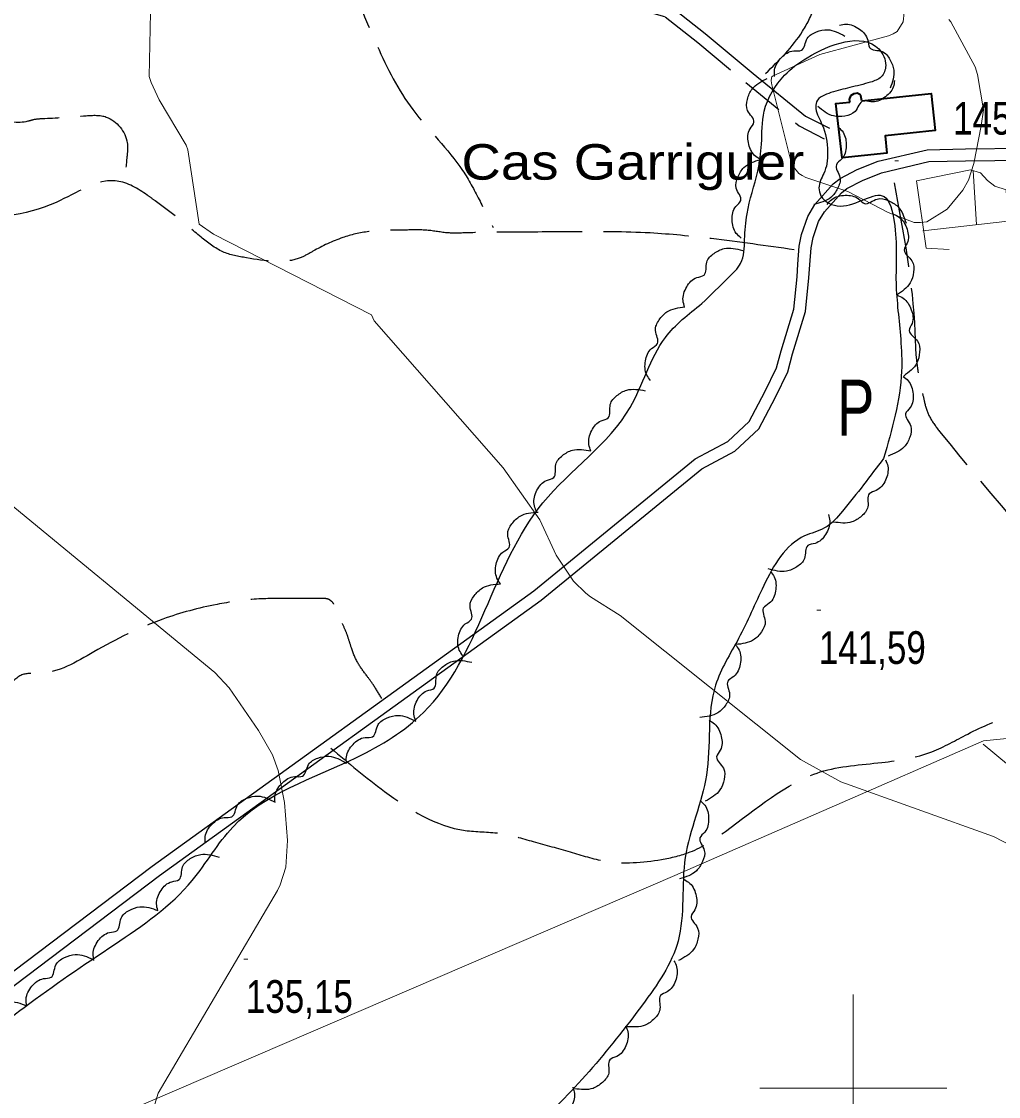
# Model space of a CAD drawing. Extents: x 483843 to 488449, y 4381269 to 4384483.
# Drawn here: x 485277.5 to 485538.8, y 4381997.7 to 4382285.4 of the extents above; entities that cross this region are included whole.
import ezdxf
from ezdxf.enums import TextEntityAlignment as Align

# ---------------------------------------------------------------- set-up
doc = ezdxf.new("R2010")
doc.units = 0
doc.header["$LTSCALE"] = 3.8
doc.linetypes.add('LONG_DASHED', pattern=[7.5, 6, -1.5])
doc.linetypes.add('MEDIUM_DASHED', pattern=[4.5, 3, -1.5])
for name, color, linetype, lineweight in [('1', 7, 'Continuous', 13), ('27', 7, 'Continuous', 25), ('38', 7, 'Continuous', 25), ('47', 7, 'Continuous', 35), ('51', 7, 'Continuous', 13), ('7', 7, 'Continuous', 13), ('9', 7, 'Continuous', 13)]:
    doc.layers.add(name, color=color, linetype=linetype, lineweight=lineweight)
doc.layers.add('31', color=7, linetype='Continuous')
doc.layers.add('5', color=7, linetype='Continuous')

msp = doc.modelspace()

# ---------------------------------------------------------------- linework, layer by layer
at = {"layer": '1'}
for p, q in [((485500, 4382025), (485500, 4381975)), ((485475, 4382000), (485525, 4382000))]:
    msp.add_line(p, q, dxfattribs=at)
at = {"layer": '27'}
for points in [[(485478.94, 4382270.69), (485478.95, 4382272.47), (485480.81, 4382275.77), (485484.07, 4382277.52), (485486.11, 4382277.69), (485487.7, 4382280.87), (485490.12, 4382282.61), (485493.09, 4382283.19), (485497.75, 4382281.5)], [(485496.32, 4382284.45), (485498.07, 4382284.71), (485501.63, 4382283.37), (485503.85, 4382280.42), (485504.33, 4382278.43), (485507.72, 4382277.35), (485509.81, 4382275.22), (485510.83, 4382272.37), (485509.87, 4382267.51)], [(485459.51, 4382209.91), (485466.62, 4382216.87), (485469.85, 4382220.68), (485470.94, 4382227.08), (485471.57, 4382233.91), (485474.44, 4382245.37), (485475.44, 4382252.59), (485476.18, 4382261.38), (485481.64, 4382271.01), (485487.63, 4382275.69), (485506.8, 4382278.06), (485508.68, 4382273.59), (485507.45, 4382270.57), (485504.63, 4382269.17), (485499.1, 4382267.72), (485494.02, 4382266.35), (485490.17, 4382263.88), (485489.97, 4382262.08), (485491.7, 4382257.76), (485493.1, 4382250.58), (485492.94, 4382247.35), (485492.08, 4382244.71), (485490.8, 4382240.86), (485491.36, 4382238.77), (485496.51, 4382236.01), (485508.25, 4382238.54), (485510.92, 4382231.84), (485511.44, 4382215.42), (485512.68, 4382200.43), (485512.91, 4382191.81), (485508.11, 4382168.47)], [(485475.04, 4382248.55), (485473.59, 4382249.58), (485471.95, 4382253), (485472.39, 4382256.67), (485473.42, 4382258.44), (485471.72, 4382261.57), (485471.68, 4382264.55), (485472.91, 4382267.31), (485476.97, 4382270.16)], [(485511.04, 4382269.59), (485510.68, 4382267.85), (485508.21, 4382264.97), (485504.68, 4382263.9), (485502.64, 4382264.13), (485500.46, 4382261.32), (485497.74, 4382260.09), (485494.72, 4382260.11), (485490.48, 4382262.68)], [(485496.08, 4382257.08), (485497.26, 4382255.75), (485498.11, 4382252.05), (485496.87, 4382248.57), (485495.47, 4382247.07), (485496.43, 4382243.65), (485495.8, 4382240.73), (485493.99, 4382238.31), (485489.4, 4382236.43)], [(485469.97, 4382227.45), (485468.7, 4382228.69), (485467.6, 4382232.32), (485468.6, 4382235.88), (485469.89, 4382237.47), (485468.69, 4382240.82), (485469.11, 4382243.77), (485470.75, 4382246.31), (485475.2, 4382248.51)], [(485493, 4382236.46), (485494.23, 4382237.76), (485497.84, 4382238.89), (485501.41, 4382237.93), (485503.02, 4382236.66), (485506.36, 4382237.89), (485509.32, 4382237.49), (485511.88, 4382235.89), (485514.12, 4382231.45)], [(485510.78, 4382233.82), (485512.34, 4382232.98), (485514.39, 4382229.79), (485514.42, 4382226.1), (485513.61, 4382224.21), (485515.69, 4382221.32), (485516.1, 4382218.36), (485515.22, 4382215.47), (485511.55, 4382212.14)], [(485454.89, 4382208.98), (485454.46, 4382210.7), (485455.43, 4382214.37), (485458.15, 4382216.87), (485460.09, 4382217.55), (485460.82, 4382221.03), (485462.74, 4382223.32), (485465.47, 4382224.62), (485470.41, 4382224.15)], [(485511.72, 4382212.15), (485513.32, 4382211.37), (485515.52, 4382208.28), (485515.71, 4382204.6), (485514.99, 4382202.67), (485517.2, 4382199.88), (485517.74, 4382196.95), (485517, 4382194.02), (485513.48, 4382190.52)], [(484798.92, 4381998.99), (484814.13, 4381997.5), (484843.2, 4381995.91), (484868.25, 4382000.56), (484887.51, 4382002.1), (484917.02, 4382005.25), (484964.05, 4382006.09), (484977.04, 4382005.57), (484983.34, 4382005.23), (485009.08, 4382005.54), (485023.48, 4382005.42), (485036.4, 4382004.83), (485065.6, 4382003.85), (485109.14, 4382007.17), (485145.01, 4382023.64), (485213.43, 4382058.32), (485219.23, 4382057.08), (485223.55, 4382050.33), (485223.76, 4382008.99), (485220.77, 4381999.7), (485221.24, 4381990.33), (485225.73, 4381986.51), (485231.26, 4381987.74), (485241.59, 4381993.47), (485278.23, 4382021.59), (485302.39, 4382038.45), (485323.17, 4382055.55), (485334.02, 4382069.85), (485367.08, 4382088.44), (485385.03, 4382100.47), (485416.97, 4382156.56), (485440.3, 4382182.11), (485449.72, 4382200.81), (485459.51, 4382209.91)], [(485445.79, 4382189.33), (485444.78, 4382190.8), (485444.39, 4382194.57), (485446.05, 4382197.87), (485447.62, 4382199.19), (485447.08, 4382202.7), (485448.06, 4382205.52), (485450.15, 4382207.7), (485454.94, 4382209.01)], [(485513.35, 4382190.43), (485514.69, 4382189.26), (485515.98, 4382185.69), (485515.19, 4382182.09), (485513.98, 4382180.42), (485515.37, 4382177.15), (485515.11, 4382174.17), (485513.61, 4382171.54), (485509.29, 4382169.11)], [(485429.81, 4382170.49), (485429.28, 4382172.19), (485430.02, 4382175.91), (485432.58, 4382178.57), (485434.47, 4382179.37), (485434.99, 4382182.89), (485436.76, 4382185.29), (485439.4, 4382186.76), (485444.36, 4382186.59)], [(485415.1, 4382154.54), (485414.59, 4382156.24), (485415.37, 4382159.95), (485417.96, 4382162.58), (485419.86, 4382163.36), (485420.42, 4382166.87), (485422.21, 4382169.26), (485424.87, 4382170.69), (485429.83, 4382170.47)], [(485508.11, 4382168.47), (485497.14, 4382154.39), (485492.34, 4382149.87), (485486.98, 4382147.75), (485476.04, 4382134.43), (485469.31, 4382120.28), (485463.15, 4382107.79), (485460.73, 4382083.73), (485455.05, 4382061.72), (485453.12, 4382039.33), (485443.59, 4382022.28), (485413.43, 4381988.65), (485371.07, 4381957.21), (485349.23, 4381936.26), (485331.41, 4381917.56), (485310.92, 4381892.36), (485301.95, 4381886.42), (485299.93, 4381877.68), (485296.95, 4381863.37), (485288.88, 4381857.75), (485280.91, 4381858.74), (485262.52, 4381888.42), (485260.4, 4381897.69), (485251.77, 4381956.74), (485244.54, 4381962.46), (485234.48, 4381967.01), (485223.41, 4381969.59), (485221.53, 4381969.55), (485200.04, 4381967.22), (485176.97, 4381960.51), (485150.46, 4381949.23), (485137.77, 4381941.58), (485118.97, 4381930.96), (485100.86, 4381928.77), (485070.67, 4381925.6), (485052.23, 4381924.67), (485034.52, 4381920.53), (485015.41, 4381919.37), (485007.52, 4381920.05), (484994.14, 4381921.24), (484952.93, 4381922.31)], [(485508.63, 4382168.07), (485509.22, 4382166.4), (485508.61, 4382162.65), (485506.15, 4382159.9), (485504.29, 4382159.03), (485503.89, 4382155.5), (485502.21, 4382153.03), (485499.62, 4382151.47), (485494.66, 4382151.46)], [(485405.62, 4382134.9), (485404.68, 4382136.41), (485404.48, 4382140.2), (485406.29, 4382143.41), (485407.92, 4382144.66), (485407.55, 4382148.19), (485408.66, 4382150.96), (485410.86, 4382153.04), (485415.7, 4382154.12)], [(485493.34, 4382153.5), (485493.7, 4382151.76), (485492.58, 4382148.13), (485489.77, 4382145.74), (485487.81, 4382145.14), (485486.93, 4382141.69), (485484.93, 4382139.48), (485482.15, 4382138.29), (485477.23, 4382138.96)], [(485477.86, 4382138.24), (485478.85, 4382136.77), (485479.2, 4382132.99), (485477.51, 4382129.71), (485475.93, 4382128.4), (485476.43, 4382124.88), (485475.43, 4382122.07), (485473.31, 4382119.91), (485468.51, 4382118.66)], [(485395.54, 4382115.68), (485394.61, 4382117.19), (485394.4, 4382120.98), (485396.21, 4382124.19), (485397.85, 4382125.44), (485397.48, 4382128.97), (485398.59, 4382131.74), (485400.78, 4382133.82), (485405.63, 4382134.9)], [(485468.44, 4382118.69), (485469.43, 4382117.21), (485469.75, 4382113.43), (485468.04, 4382110.16), (485466.44, 4382108.87), (485466.92, 4382105.34), (485465.89, 4382102.54), (485463.76, 4382100.4), (485458.95, 4382099.17)], [(485382.93, 4382098.29), (485382.45, 4382100), (485383.31, 4382103.69), (485385.95, 4382106.28), (485387.87, 4382107.01), (485388.5, 4382110.51), (485390.34, 4382112.86), (485393.03, 4382114.24), (485397.98, 4382113.92)], [(485364.44, 4382086.82), (485364.41, 4382088.6), (485366.17, 4382091.95), (485369.38, 4382093.79), (485371.42, 4382094.02), (485372.91, 4382097.24), (485375.29, 4382099.05), (485378.24, 4382099.71), (485382.95, 4382098.15)], [(485461.42, 4382098.42), (485462.9, 4382097.45), (485464.69, 4382094.1), (485464.41, 4382090.42), (485463.45, 4382088.6), (485465.28, 4382085.55), (485465.44, 4382082.57), (485464.33, 4382079.76), (485460.39, 4382076.74)], [(485345.27, 4382076.64), (485345.33, 4382078.42), (485347.27, 4382081.67), (485350.57, 4382083.33), (485352.62, 4382083.45), (485354.29, 4382086.59), (485356.76, 4382088.27), (485359.74, 4382088.77), (485364.36, 4382086.96)], [(485326.62, 4382065.53), (485326.63, 4382067.3), (485328.47, 4382070.62), (485331.71, 4382072.39), (485333.75, 4382072.58), (485335.31, 4382075.77), (485337.73, 4382077.53), (485340.69, 4382078.13), (485345.37, 4382076.47)], [(485459, 4382076.95), (485460.25, 4382075.7), (485461.31, 4382072.06), (485460.28, 4382068.51), (485458.97, 4382066.93), (485460.14, 4382063.57), (485459.68, 4382060.62), (485458.02, 4382058.1), (485453.54, 4382055.95)], [(485313.94, 4382047.54), (485313.62, 4382049.29), (485314.81, 4382052.89), (485317.67, 4382055.22), (485319.64, 4382055.79), (485320.59, 4382059.21), (485322.63, 4382061.39), (485325.44, 4382062.52), (485330.34, 4382061.75)], [(485454.81, 4382055.78), (485456.28, 4382054.77), (485457.98, 4382051.38), (485457.61, 4382047.71), (485456.61, 4382045.91), (485458.36, 4382042.82), (485458.45, 4382039.84), (485457.27, 4382037.05), (485453.26, 4382034.13)], [(485296.87, 4382034.14), (485296.64, 4382035.9), (485298.02, 4382039.44), (485300.99, 4382041.62), (485302.99, 4382042.08), (485304.12, 4382045.45), (485306.27, 4382047.52), (485309.13, 4382048.5), (485313.98, 4382047.49)], [(485278.85, 4382022.03), (485278.71, 4382023.8), (485280.28, 4382027.25), (485283.36, 4382029.28), (485285.39, 4382029.63), (485286.68, 4382032.94), (485288.95, 4382034.89), (485291.85, 4382035.72), (485296.65, 4382034.45)], [(485452.01, 4382034.08), (485452.73, 4382032.46), (485452.42, 4382028.68), (485450.19, 4382025.74), (485448.4, 4382024.73), (485448.28, 4382021.18), (485446.8, 4382018.58), (485444.34, 4382016.83), (485439.4, 4382016.42)], [(485261.6, 4382008.87), (485261.38, 4382010.63), (485262.79, 4382014.16), (485265.79, 4382016.31), (485267.8, 4382016.75), (485268.95, 4382020.11), (485271.13, 4382022.15), (485274, 4382023.11), (485278.84, 4382022.04)], [(485439.06, 4382016.68), (485439.69, 4382015.02), (485439.15, 4382011.26), (485436.74, 4382008.46), (485434.89, 4382007.56), (485434.57, 4382004.02), (485432.93, 4382001.52), (485430.37, 4381999.91), (485425.41, 4381999.81)], [(485424.95, 4382000.22), (485425.4, 4381998.51), (485424.47, 4381994.83), (485421.79, 4381992.29), (485419.86, 4381991.59), (485419.17, 4381988.1), (485417.29, 4381985.78), (485414.58, 4381984.45), (485409.63, 4381984.85)]]:
    msp.add_spline(points, degree=3, dxfattribs=at)
at = {"layer": '38'}
for points in [[(485435.92, 4382293.7), (485439.33, 4382292.86), (485451.11, 4382289.47), (485460.37, 4382282.19), (485473.24, 4382271.47), (485487.22, 4382260.09), (485493.63, 4382256.82)], [(485235.03, 4382000.84), (485312.48, 4382059.39), (485414.56, 4382133.08), (485457.71, 4382168.4), (485466.46, 4382173.04), (485472.13, 4382178.33), (485476.36, 4382186.32), (485479.5, 4382192.75), (485480.67, 4382197.29), (485484.08, 4382208.4), (485484.95, 4382217.04), (485485.19, 4382220.49), (485485.56, 4382225.26), (485486.12, 4382228.44), (485487.82, 4382233.25), (485489.71, 4382236.4), (485494.65, 4382241.92), (485496.53, 4382243.38), (485501.07, 4382245.75), (485506.61, 4382247.98), (485519.8, 4382251.09), (485530.01, 4382251.28), (485545.6, 4382251.48)], [(485236.96, 4381998.29), (485314.38, 4382056.83), (485416.5, 4382130.54), (485459.49, 4382165.73), (485468.33, 4382170.41), (485474.71, 4382176.36), (485479.21, 4382184.87), (485482.52, 4382191.64), (485483.76, 4382196.43), (485487.22, 4382207.77), (485488.14, 4382216.77), (485488.38, 4382220.26), (485488.74, 4382224.86), (485489.23, 4382227.63), (485490.72, 4382231.88), (485492.29, 4382234.49), (485496.84, 4382239.57), (485498.26, 4382240.68), (485502.42, 4382242.85), (485507.57, 4382244.93), (485520.2, 4382247.91), (485530.06, 4382248.08), (485545.69, 4382248.28)]]:
    msp.add_lwpolyline(points, dxfattribs=at)
at = {"layer": '38', "linetype": 'MEDIUM_DASHED'}
msp.add_lwpolyline([(485435.17, 4382290.68), (485438.52, 4382289.84), (485449.66, 4382286.64), (485458.41, 4382279.77), (485471.26, 4382269.06), (485485.51, 4382257.46), (485492.21, 4382254.04)], dxfattribs=at)
at = {"layer": '38', "linetype": 'LONG_DASHED'}
for points in [[(485476.53, 4382271.44), (485486.45, 4382282.8), (485489.78, 4382289.76), (485492.8, 4382330.78), (485507.2, 4382373.28), (485507.25, 4382395.64), (485506.93, 4382400.97), (485504.7, 4382412.63), (485509.62, 4382423), (485512.91, 4382427.71), (485519.46, 4382443.28), (485523.09, 4382454.75), (485524.19, 4382460.32), (485526.24, 4382475.89), (485527.73, 4382493.1), (485527.34, 4382498.05), (485527.57, 4382510.28), (485534.14, 4382529.16), (485535.62, 4382530.26)], [(485355.21, 4382332.66), (485360.95, 4382310.58), (485372.62, 4382278.9), (485382.16, 4382261.81), (485395.5, 4382245.54), (485399.92, 4382237.74), (485403.65, 4382230.31)], [(484788.33, 4382234.74), (484798.67, 4382230.05), (484803.24, 4382234.63), (484824.91, 4382247.7), (484836.04, 4382250.97), (484859.06, 4382259.93), (484874.65, 4382269.29), (484884.56, 4382273.37), (484899.83, 4382279.49), (484900.61, 4382282.21), (484903.87, 4382284.59), (484911.85, 4382286.98), (484915.45, 4382287.05), (484917.93, 4382287.09), (484921.74, 4382288.06), (484928.22, 4382290.95), (484942.69, 4382299.91), (484969.07, 4382306.01), (484978.82, 4382306.18), (484999.64, 4382308.28), (485005.36, 4382307.03), (485017.7, 4382301.17), (485026.64, 4382300.21), (485028.22, 4382300.23), (485050.5, 4382291.78), (485074.9, 4382295.36), (485078.11, 4382296.09), (485099.65, 4382296.25), (485110.05, 4382293.74), (485115.9, 4382293.69), (485123.47, 4382294.05), (485131.94, 4382294.8), (485145.49, 4382296.47), (485158.78, 4382295.88), (485165.4, 4382294.65), (485166.94, 4382292.8), (485169.07, 4382290.73), (485175.72, 4382288.08), (485189.84, 4382283.45), (485200.22, 4382277.78), (485213.12, 4382269.31), (485218.12, 4382266.85), (485223.91, 4382265.9), (485231.94, 4382265.82), (485237.5, 4382265.92), (485249.13, 4382265.67), (485262.09, 4382262.6), (485279.27, 4382258.78), (485280.83, 4382259.18), (485283.75, 4382259.46), (485294.77, 4382260.18), (485300.18, 4382259.83), (485305.78, 4382252.95), (485305.7, 4382249.2), (485305.14, 4382242.81)], [(485484.19, 4382224.31), (485462, 4382227.29), (485445.62, 4382228.8), (485425.21, 4382229.11), (485406, 4382229), (485396.4, 4382228.83), (485391.67, 4382228.82), (485385.88, 4382229.54), (485380.78, 4382229.6), (485373.58, 4382229.47), (485370.36, 4382229.19), (485363.41, 4382227.56), (485355.44, 4382223.9), (485352.32, 4382222.26), (485337.69, 4382222.15), (485331.36, 4382223.77), (485325.51, 4382227.71), (485318.96, 4382233.08), (485313.26, 4382237.4), (485311.13, 4382238.94), (485303.04, 4382242.7), (485286.78, 4382237), (485260.76, 4382231.74), (485235.93, 4382227.55), (485209.66, 4382223.4), (485193.33, 4382217.71), (485185.4, 4382212.09), (485179.16, 4382208.75), (485156.32, 4382197.92), (485147.1, 4382193.18), (485130.6, 4382184.18), (485114.63, 4382179.54), (485097.49, 4382172.64), (485085.86, 4382172.65), (485070.41, 4382172.45), (485061.41, 4382172.22), (485054.83, 4382171.13), (485047.82, 4382168.75), (485042.14, 4382163.02), (485025.23, 4382156.04), (485007.3, 4382147.7), (484996.93, 4382143.99), (484984.86, 4382143.85), (484972.93, 4382143.41), (484965.15, 4382142.37), (484941.34, 4382135.49), (484910.04, 4382127.36), (484902.35, 4382129.25), (484885.33, 4382158.51), (484879.28, 4382161.03), (484869.89, 4382165.81), (484839.61, 4382176.53), (484822.23, 4382174.87), (484818.62, 4382175.7), (484809.9, 4382176.45), (484809.97, 4382176.6), (484803.91, 4382175.74), (484793.66, 4382182.46), (484789.53, 4382186.8)], [(485510.89, 4382242.19), (485516.47, 4382202.37), (485516.81, 4382195.7), (485517.17, 4382192.71), (485517.51, 4382190.16), (485517.85, 4382187.99), (485518.25, 4382186.8), (485519.06, 4382183.44), (485520.48, 4382179.49), (485523.1, 4382175.71), (485567.25, 4382123.22), (485573.4, 4382114.77), (485577.13, 4382107.79), (485580.83, 4382101.93), (485584.62, 4382095.99), (485584.45, 4382084.43), (485582.73, 4382075.77), (485580.04, 4382057.79), (485579.45, 4382048.85), (485578.24, 4382040.95), (485577.05, 4382031.93), (485575.68, 4382016.52), (485576.68, 4382010.69), (485580.74, 4381997.48), (485592.32, 4381983.65), (485596.88, 4381976.16), (485602.51, 4381967.55), (485610.17, 4381958.54), (485617.52, 4381950.49), (485628.68, 4381939.13), (485637.55, 4381929.39), (485644.89, 4381922.01), (485650.99, 4381916.49), (485652.89, 4381914.8), (485660.78, 4381905.71), (485662.66, 4381901.39), (485663.57, 4381896.53), (485663.65, 4381892.18), (485661.62, 4381875.42), (485658.97, 4381868.76), (485655.84, 4381858.88), (485655.45, 4381851.14), (485657.4, 4381842.7), (485660.42, 4381837.58), (485665.75, 4381824.99), (485667.34, 4381820.57)], [(485360.28, 4382090.95), (485374.6, 4382079.35), (485396.17, 4382068.93), (485405.26, 4382068.19), (485414.38, 4382065.95), (485424.26, 4382063.2), (485433.53, 4382060.74), (485448.68, 4382061.16), (485456.37, 4382063.17), (485465.8, 4382068.67), (485491.18, 4382084.57), (485507.64, 4382087.12), (485521.02, 4382089.98), (485530.62, 4382094.73), (485542.75, 4382099.97), (485551.11, 4382102.67), (485559.63, 4382104.63), (485566.71, 4382107.08), (485587.31, 4382113.07), (485625.88, 4382134.47), (485645.38, 4382147.12), (485660.03, 4382154.58), (485679.03, 4382166.63), (485686.62, 4382169.91), (485739.51, 4382187.21), (485745.48, 4382209.98), (485777.15, 4382230.95), (485786.69, 4382238.52)], [(485373.85, 4382104.25), (485371.61, 4382107.88), (485369.84, 4382110.33), (485367.53, 4382113.66), (485365.74, 4382117.76), (485364.86, 4382120.59), (485363.99, 4382122.83), (485362.82, 4382125.58), (485361.95, 4382127.89), (485361.25, 4382129.23), (485360.49, 4382130.19), (485359.12, 4382130.92), (485358.07, 4382130.98), (485349.52, 4382130.97), (485339.77, 4382130.8), (485329.81, 4382129.42), (485315.33, 4382125.49), (485296.8, 4382116.68), (485282.05, 4382110.94), (485277.62, 4382110.56), (485273.18, 4382107.56), (485271.38, 4382107.15), (485266.13, 4382106.98), (485264.41, 4382106.88), (485261.79, 4382106.53), (485260.82, 4382106.29), (485257.54, 4382105.03), (485256.95, 4382104.57), (485254.28, 4382102.42), (485251.82, 4382097.42), (485248.43, 4382090.01), (485245.65, 4382081.71), (485244.91, 4382076.97), (485244.42, 4382070.58), (485244.45, 4382064.5)]]:
    msp.add_spline(points, degree=3, dxfattribs=at)
at = {"layer": '47'}
for points in [[(485502.25, 4382264.18), (485520.81, 4382266.15), (485521.86, 4382256.22), (485508.49, 4382254.81), (485508.98, 4382250.13), (485497.05, 4382248.95), (485495.35, 4382263.45), (485499.04, 4382263.84)], [(485502.25, 4382264.18), (485501.99, 4382265.52), (485501.76, 4382265.82), (485501.53, 4382265.96), (485501.08, 4382266.18), (485500.71, 4382266.17), (485500.11, 4382266.01), (485499.66, 4382265.78), (485499.29, 4382265.47), (485498.93, 4382264.56), (485499.04, 4382263.84)]]:
    msp.add_lwpolyline(points, dxfattribs=at)
at = {"layer": '51'}
for p, q in [((485532.09, 4382245.48), (485532.95, 4382231.02)), ((485534.72, 4382092.03), (485572.95, 4382060.22))]:
    msp.add_line(p, q, dxfattribs=at)
for points in [[(485518.62, 4382229.35), (485541.3, 4382232), (485540.93, 4382240.33), (485537.84, 4382241.32), (485535.93, 4382242.86), (485534.02, 4382244.86), (485531.38, 4382245.71), (485516.95, 4382242.75)], [(485516.95, 4382242.75), (485519.45, 4382224.71), (485525.61, 4382224.37)], [(484797.38, 4381871.67), (484872.36, 4381871.2), (485020.85, 4381871.14), (485147.28, 4381925.69), (485256.22, 4381972.5), (485452.28, 4382056.87), (485534.85, 4382092.93), (485579.79, 4382097.33)]]:
    msp.add_lwpolyline(points, dxfattribs=at)
at = {"layer": '7'}
for p, q in [((485511.11, 4382248.13), (485512.11, 4382248.13)), ((485490.28, 4382127.86), (485491.28, 4382127.86)), ((485337, 4382034.49), (485338, 4382034.49))]:
    msp.add_line(p, q, dxfattribs=at)
at = {"layer": '9'}
for points in [[(485312.09, 4382292.17), (485311.67, 4382270.68), (485312.22, 4382269.09), (485314.31, 4382264.46), (485321.54, 4382252.33), (485321.96, 4382251.06), (485324.99, 4382231.14), (485328.87, 4382228.47), (485371.1, 4382206.91), (485371.87, 4382205.31), (485406.3, 4382165.93), (485416.12, 4382152.06), (485420.5, 4382142.57), (485425.16, 4382135.63), (485428.44, 4382132.42), (485429.72, 4382131.44), (485437.65, 4382126.44), (485485.86, 4382087.89), (485496.67, 4382081.95), (485537.54, 4382067.35), (485545.61, 4382063.16)], [(485513.61, 4382287.82), (485513.33, 4382285.28), (485511.72, 4382282.75), (485510.69, 4382282.12), (485509.4, 4382281.52), (485491.02, 4382276.57), (485478.36, 4382270.77), (485478.19, 4382270.58), (485478.13, 4382270.32), (485478.07, 4382269.54), (485478.17, 4382268.49), (485483.52, 4382247.07), (485485.42, 4382244.76), (485486.29, 4382244.19), (485487.32, 4382243.66), (485498.55, 4382239.92), (485509.35, 4382234.27), (485516.26, 4382231.62), (485518.01, 4382231.57), (485519.69, 4382231.81), (485525.14, 4382235.17), (485529.26, 4382240.26), (485530.81, 4382242.92), (485532.28, 4382247.41), (485534.24, 4382257.48), (485534.84, 4382261.78), (485533.26, 4382271.17), (485532.56, 4382273.24), (485526.13, 4382285.26), (485525.59, 4382285.91)], [(485268.03, 4382161.49), (485329.23, 4382111.16), (485333.02, 4382107.11), (485340.85, 4382095.7), (485344.59, 4382089.13), (485346.11, 4382084.95), (485347.84, 4382076.39), (485348.63, 4382066.2), (485348.21, 4382059.12), (485346.68, 4382054.35), (485346, 4382052.88), (485314.07, 4381998.63), (485308.1, 4381978.78)]]:
    msp.add_lwpolyline(points, dxfattribs=at)

# ---------------------------------------------------------------- texts
at = {"layer": '31', "width": 0.75}
msp.add_text('P', height=15, dxfattribs=at).set_placement((485500.63, 4382174.57), align=Align.CENTER)
at = {"layer": '5', "width": 1.15}
msp.add_text('Cas Garriguer', height=9.5, dxfattribs=at).set_placement((485395.17, 4382243.07))
at = {"layer": '7', "width": 0.8}
for s, p in [('145,75', (485526.7, 4382255.12)), ('141,59', (485490.78, 4382113.49)), ('135,15', (485337.5, 4382020.12))]:
    msp.add_text(s, height=8.75, dxfattribs=at).set_placement(p)

doc.saveas('drawing.dxf')
